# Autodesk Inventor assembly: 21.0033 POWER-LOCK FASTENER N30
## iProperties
Created: 2012-10
Part Number: 21.0033 POWER-LOCK FASTENER N30
Document SubType Name: Assembly
Designer: Administrator
Author: Administrator
